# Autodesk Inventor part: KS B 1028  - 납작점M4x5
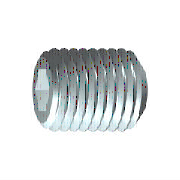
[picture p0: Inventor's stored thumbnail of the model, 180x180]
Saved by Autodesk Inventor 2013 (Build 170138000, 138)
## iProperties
IsCustomPart: 0
Created: 2009-02
Part Number: KS B 1028  - 납작점M4x5
Material: 강철, 연강
Description: 6각 소켓 머리 없는 멈춤 나사
Document SubType Name: Modeling
Standard: KS B 1028
Designer: KYOUNG IL JANG
Standards Organization: KS
Language: ko-KR
Size Designation: 납작점M4x5
Categories: <MemberInstance><Categories><Category DisplayName="조임쇠" InternalName="e4da775c-781d-43d5-af7c-5136215cf5a6" Mnemonic="FSTN"><Category DisplayName="볼트" InternalN
Density: 1 g/cm^3
Author: KYOUNG IL JANG
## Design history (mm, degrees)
sketch "스케치1"
  geometry: L1 (0, 0)-(1.833, 0); L2 (5, 1.155)-(5, 2); L3 (5, 2)-(0, 2); L4 (5, 1.155)-(2.5, 1.155); L5 (2.5, 1.155)-(1.833, 0); L6 (0, -0.4)-(0, 2.4) reference; L7 (0, 2)-(0, 0)
  constraints: 13 end point, 3 parallel, 1 collinear, 1 perpendicular, 1 point on line
  dimensions: "d0" = 2.5 distance of L2.start L4.end (= INTI); "d1" = 60 deg angle of L5 L1; "d2" = 4 diameter of L3 L1 (= NND); "d3" = 2.3094 diameter of L4 L1 (= 1.1547 x SW); "d5" = 5 distance from line of L2 L3.end (= NLG)
revolve "본체" sketch "스케치1" stored, may be unused: angle "d6" = 90 deg
sketch "스케치2"
  geometry: L1 (-0.577, 1)-(0.577, 1); L2 (0.577, 1)-(1.155, 0); L3 (1.155, 0)-(0.577, -1); L4 (0.577, -1)-(-0.577, -1); L5 (-0.577, -1)-(-1.155, 0); L6 (-1.155, 0)-(-0.577, 1); A1 r 1.155 centre (0, 0) between (-0.577, 1) and (0.577, 1) reference; 2 further points
  constraints: 12 end point, 2 point on circle, 1 coincident, 1 horizontal, 11 other
extrude "슬롯" join sketch "스케치2" taper "d9" = 0 deg; stored distance "d21" = 10
workaxis "Work Axis1"
workplane "Work Plane1"
body "Solid1"
chamfer "모따기1" distance "d7" = 0.42941 (= -0.5 x GD1 + 0.5 x NND); stored, may be unused: angle "d8" = 45 deg (= FAWI), second distance "d29" = 0.42941 (= -0.5 x GD1 + 0.5 x NND)
feature "스레드" dims "d11" = 5 (= NLG), "d12" = 0
chamfer "모따기2" distance "d13" = 0.42941 (= -0.5 x GD1 + 0.5 x NND); stored, may be unused: angle "d14" = 45 deg (= FAWI), second distance "d30" = 0.42941 (= -0.5 x GD1 + 0.5 x NND)
other parameters: "NND" = 4 [user parameter; used in 5 equation terms], "NLG" = 5 [user parameter; used in 2 equation terms], "INTI" = 2.5 [user parameter; used in 1 equation term], "FAWI" = 45 deg [user parameter; used in 2 equation terms], "SW" = 2 [user parameter; used in 2 equation terms], "GD1" = 3.14117 (= THREADDIA - 1.2269 x PTC) [user parameter; used in 4 equation terms], "d4" = 0, "FAWI1" = 45 deg [user parameter], "d15" = 0, "d31" = 0, "GUL" = 0.42941 (= 0.61345 x PTC) [user parameter], "SPD" = 2.5 [user parameter], "TPU" = 14.28571 (computed from PTC) [user parameter], "TOA" = 30 deg [user parameter], "THREADDIA" = 4 [user parameter; used in 1 equation term], "PTC" = 0.7 [user parameter; used in 4 equation terms], "GAL" = 0.42941 (= 0.61345 x PTC) [user parameter], "E0" = 2.31 (= 1.155 x SW) [user parameter]
